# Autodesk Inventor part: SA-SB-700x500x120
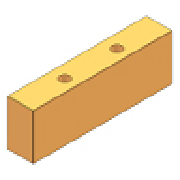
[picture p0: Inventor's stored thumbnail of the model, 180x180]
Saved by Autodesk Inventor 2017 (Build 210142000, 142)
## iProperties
Created: 2016-02
Part Number: SA-SB-700x500x120
Material: S 55 C
Description: Spacer Block
Document SubType Name: Modeling
Designer: Sandeep
Standard Revision: 1
Manufacturer: FUTABA
Language: en-US
Size Designation: 700x500x120
Categories: <MemberInstance><Categories><Category DisplayName="Mold" InternalName="349578f2-f4d4-4954-8c09-8e99297a61c0" Mnemonic="MOLD"><Category DisplayName="Mold Plates"
Density: 7.85 g/cm^3
Appearance: Orange (Pale)
IsCustomPart: 1
Author: Sandeep
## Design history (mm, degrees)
sketch "Sketch1"
  geometry: L1 (-162, 350)-(-250, 350); L2 (-250, 350)-(-250, -350); L3 (-250, -350)-(-162, -350); L4 (-162, -350)-(-162, 350); L5 (250, 350)-(250, -350); L6 (162, -350)-(162, 350); L7 (162, 350)-(250, 350); L8 (162, -350)-(250, -350); 5 further points
  constraints: 16 end point, 3 parallel, 2 horizontal alignment, 2 midpoint, 2 perpendicular, 1 horizontal, 1 vertical
  dimensions: "d85" = 700 distance between parallel lines of L3 L1 (= L); "d86" = 88 distance between parallel lines of L4 L2 (= W_); "d88" = 88 distance between parallel lines of L5 L6 (= W_); "d89" = 250 distance from line of point (0, 0) L2 (= 0.5 x M_W); "d93" = 700 distance between parallel lines of L8 L7 (= L); "d94" = 250 distance from line of point (0, 0) L5 (= 0.5 x M_W); "d98" = 243 vertical distance of point (-205, 243) point (0, 0) (= 0.5 x S1_L); "d100" = 205 horizontal distance of point (-205, 243) point (0, 0) (= 0.5 x S1_W); "d101" = 205 horizontal distance of point (205, 243) point (0, 0) (= 0.5 x S1_W); "d102" = 243 vertical distance of point (0, 0) point (205, 243) (= 0.5 x S1_L)
extrude "Extrusion1" new body sketch "Sketch1" distance "d20" = 120 (= H_); taper "d30" = 0 deg
extrude "Extrusion2" join sketch "Sketch1" distance "d95" = 120 (= H_); taper "d96" = 0 deg
workplane "Work Plane2"
body "Solid1"
hole "Hole1" sketch "Sketch1" diameter "d129" = 18 (= S1_d1); stored, may be unused: countersink angle "d133" = 90 deg, drill point angle "d135" = 0 deg; dims "d130" = 6, "d131" = 4, "d132" = 2, "d134" = 120 (= H_)
pattern_linear "Rectangular Pattern1" dims "d156" = 243 (computed from S1_L, Ns)
hole "Hole2" sketch "Sketch1" diameter "d122" = 18 (= S1_d1); stored, may be unused: countersink angle "d126" = 90 deg, drill point angle "d128" = 0 deg; dims "d123" = 6, "d124" = 4, "d125" = 2, "d127" = 120 (= H_)
pattern_linear "Rectangular Pattern2" dims "d153" = 243 (computed from S1_L, Ns)
workplane "Work Plane1"
chamfer "Chamfer1" distance "d157" = 0.5; stored, may be unused: second distance "d158" = 2, angle "d159" = 45 deg
chamfer "Chamfer2" distance "d160" = 0.5; stored, may be unused: second distance "d161" = 2, angle "d162" = 45 deg
other parameters: "L" = 700 [user parameter; used in 2 equation terms], "W_" = 88 [user parameter; used in 2 equation terms], "H_" = 120 [user parameter; used in 5 equation terms], "S1_L" = 486 [user parameter; used in 4 equation terms], "S1_d1" = 18 [user parameter; used in 2 equation terms], "d164" = 0
